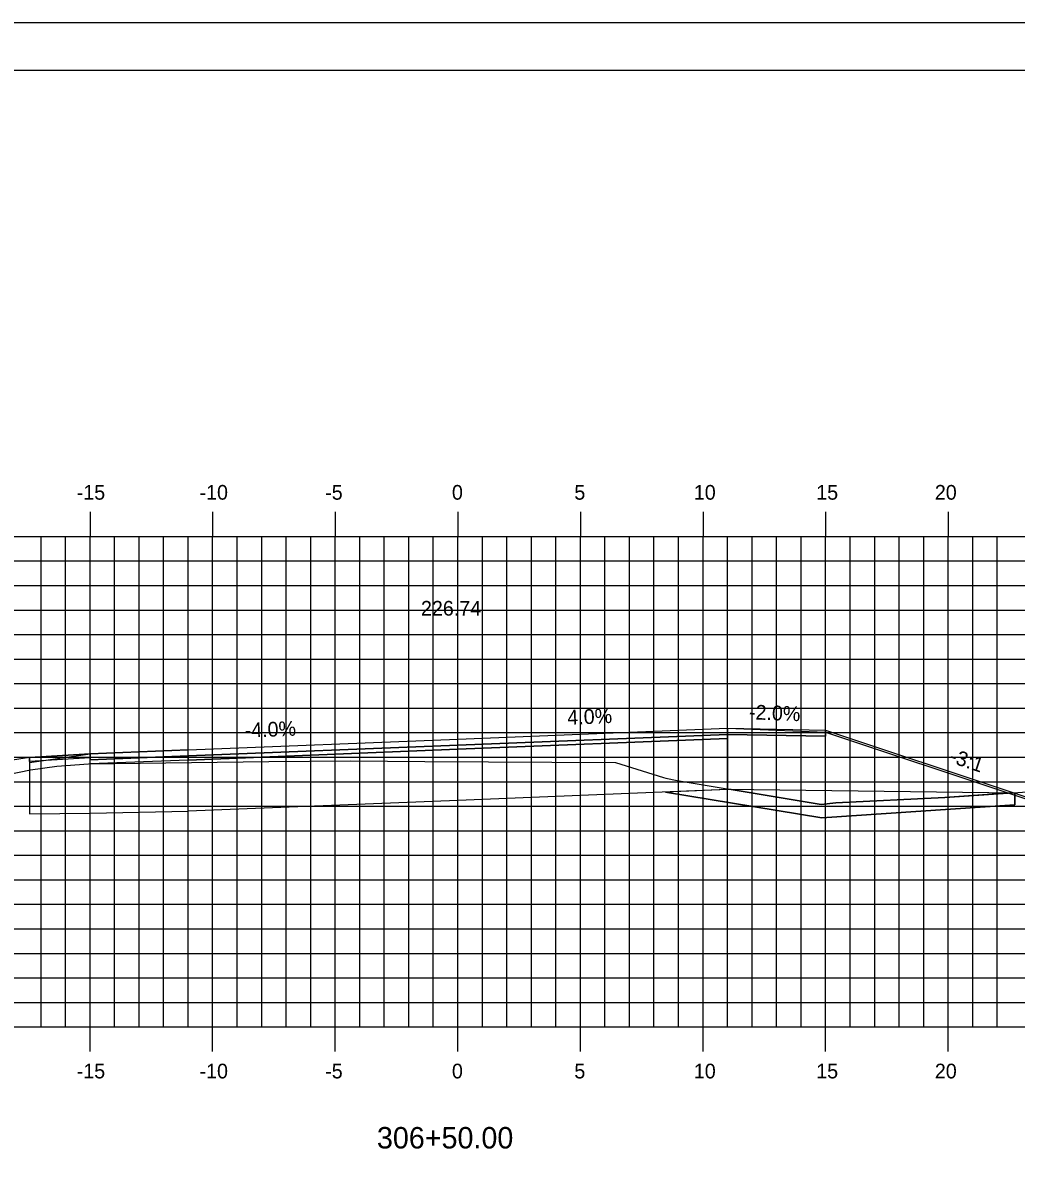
# Model space of a CAD drawing. Extents: x 1137433 to 1137603, y 608981 to 609091.
# Drawn here: x 1137497.92 to 1137538.42, y 609044.46 to 609091.28 of the extents above; entities that cross this region are included whole.
import ezdxf

# ---------------------------------------------------------------- set-up
doc = ezdxf.new("R2010")
doc.units = 0
for name, color, linetype in [('ANNOTATION', 7, 'Continuous'), ('BORDER', 7, 'Continuous'), ('D_Roadway_Centerline', 7, 'Continuous'), ('D_Roadway_Centerline_Text', 7, 'Continuous'), ('D_Roadway_Edge_Shoulder', 7, 'Continuous'), ('D_Roadway_Edge_TW', 7, 'Continuous'), ('D_Roadway_Pavement', 7, 'Continuous'), ('D_Roadway_SlopeLines', 7, 'Continuous'), ('D_Roadway_SubGrade', 7, 'Continuous'), ('H_V ANNOTATION', 7, 'Continuous'), ('MAJOR', 7, 'Continuous'), ('MINOR', 7, 'Continuous'), ('PATTERNING', 7, 'Continuous'), ('PLOT BOUNDARY', 7, 'Continuous'), ('S_Roadway_Centerline', 7, 'Continuous'), ('SHADING', 7, 'Continuous')]:
    doc.layers.add(name, color=color, linetype=linetype)

msp = doc.modelspace()

# ---------------------------------------------------------------- linework, layer by layer
msp.add_lwpolyline([(1137498.181, 609061.117), (1137500.653, 609061.475), (1137504.653, 609061.635), (1137515.653, 609062.075), (1137526.653, 609062.515), (1137530.653, 609062.355), (1137538.376, 609059.781), (1137541.376, 609058.781), (1137541.866, 609059.026), (1137543.116, 609059.579), (1137544.366, 609059.988), (1137545.616, 609060.252), (1137546.866, 609060.373)])
at = {"layer": 'ANNOTATION'}
msp.add_line((1137498.181, 609061.327), (1137477.623, 609058.046), dxfattribs=at)
at = {"layer": 'BORDER'}
msp.add_lwpolyline([(1137440.653, 608984.335), (1137600.653, 608984.335), (1137600.653, 609089.335), (1137440.653, 609089.335)], close=True, dxfattribs=at)
at = {"layer": 'D_Roadway_Edge_Shoulder'}
for points in [[(1137526.653, 609062.515), (1137530.653, 609062.435), (1137530.653, 609062.185), (1137526.653, 609062.265)], [(1137500.653, 609061.475), (1137500.653, 609061.309), (1137498.181, 609061.16), (1137498.181, 609061.327)], [(1137504.653, 609061.635), (1137500.653, 609061.475), (1137500.653, 609061.225), (1137504.653, 609061.385)]]:
    msp.add_lwpolyline(points, close=True, dxfattribs=at)
at = {"layer": 'D_Roadway_Edge_TW'}
for points in [[(1137504.653, 609061.385), (1137504.653, 609061.635), (1137515.653, 609062.075), (1137526.653, 609062.515), (1137526.653, 609062.265), (1137515.653, 609061.825)], [(1137504.653, 609061.219), (1137500.652, 609061.059), (1137500.653, 609061.225), (1137504.653, 609061.385)]]:
    msp.add_lwpolyline(points, close=True, dxfattribs=at)
at = {"layer": 'D_Roadway_Pavement'}
msp.add_lwpolyline([(1137504.653, 609061.219), (1137504.653, 609061.385), (1137515.653, 609061.825), (1137526.653, 609062.265), (1137526.653, 609062.099), (1137515.653, 609061.659)], close=True, dxfattribs=at)
at = {"layer": 'D_Roadway_SlopeLines'}
for points in [[(1137538.376, 609059.861), (1137538.376, 609059.39), (1137530.503, 609058.855), (1137524.125, 609059.914)], [(1137538.376, 609059.861), (1137541.376, 609058.861)]]:
    msp.add_lwpolyline(points, dxfattribs=at)
at = {"layer": 'D_Roadway_SubGrade'}
for points in [[(1137526.653, 609062.099), (1137526.653, 609062.265), (1137530.653, 609062.185), (1137530.653, 609062.435), (1137530.653, 609062.435), (1137538.376, 609059.861), (1137526.653, 609060.015)], [(1137504.653, 609059.135), (1137504.653, 609061.219), (1137515.653, 609061.659), (1137526.653, 609062.099), (1137526.653, 609060.015), (1137515.653, 609059.575)], [(1137498.18, 609059.023), (1137500.653, 609059.055), (1137504.653, 609059.135), (1137504.653, 609061.219), (1137504.653, 609061.385), (1137500.653, 609061.225), (1137500.653, 609061.475), (1137498.181, 609061.327)]]:
    msp.add_lwpolyline(points, close=True, dxfattribs=at)
at = {"layer": 'MAJOR'}
for p, q in [((1137500.653, 609071.337), (1137500.653, 609070.335)), ((1137505.653, 609071.337), (1137505.653, 609070.335)), ((1137510.653, 609071.337), (1137510.653, 609070.335)), ((1137515.653, 609071.337), (1137515.653, 609070.335)), ((1137520.653, 609071.337), (1137520.653, 609070.335)), ((1137525.653, 609071.337), (1137525.653, 609070.335)), ((1137530.653, 609071.337), (1137530.653, 609070.335)), ((1137535.653, 609071.337), (1137535.653, 609070.335)), ((1137445.653, 609070.335), (1137585.653, 609070.335)), ((1137445.653, 609070.335), (1137585.653, 609070.335)), ((1137500.653, 609050.335), (1137500.653, 609070.335)), ((1137505.653, 609050.335), (1137505.653, 609070.335)), ((1137510.653, 609050.335), (1137510.653, 609070.335)), ((1137515.653, 609050.335), (1137515.653, 609070.335)), ((1137520.653, 609050.335), (1137520.653, 609070.335)), ((1137525.653, 609050.335), (1137525.653, 609070.335)), ((1137530.653, 609050.335), (1137530.653, 609070.335)), ((1137535.653, 609050.335), (1137535.653, 609070.335)), ((1137445.653, 609065.335), (1137585.653, 609065.335)), ((1137445.653, 609060.335), (1137585.653, 609060.335)), ((1137445.653, 609055.335), (1137585.653, 609055.335)), ((1137445.653, 609050.335), (1137585.653, 609050.335)), ((1137445.653, 609050.335), (1137585.653, 609050.335)), ((1137500.653, 609049.333), (1137500.653, 609050.335)), ((1137505.653, 609049.333), (1137505.653, 609050.335)), ((1137510.653, 609049.333), (1137510.653, 609050.335)), ((1137515.653, 609049.333), (1137515.653, 609050.335)), ((1137520.653, 609049.333), (1137520.653, 609050.335)), ((1137525.653, 609049.333), (1137525.653, 609050.335)), ((1137530.653, 609049.333), (1137530.653, 609050.335)), ((1137535.653, 609049.333), (1137535.653, 609050.335))]:
    msp.add_line(p, q, dxfattribs=at)
at = {"layer": 'MINOR'}
for p, q in [((1137498.653, 609050.335), (1137498.653, 609070.335)), ((1137499.653, 609050.335), (1137499.653, 609070.335)), ((1137501.653, 609050.335), (1137501.653, 609070.335)), ((1137502.653, 609050.335), (1137502.653, 609070.335)), ((1137503.653, 609050.335), (1137503.653, 609070.335)), ((1137504.653, 609050.335), (1137504.653, 609070.335)), ((1137506.653, 609050.335), (1137506.653, 609070.335)), ((1137507.653, 609050.335), (1137507.653, 609070.335)), ((1137508.653, 609050.335), (1137508.653, 609070.335)), ((1137509.653, 609050.335), (1137509.653, 609070.335)), ((1137511.653, 609050.335), (1137511.653, 609070.335)), ((1137512.653, 609050.335), (1137512.653, 609070.335)), ((1137513.653, 609050.335), (1137513.653, 609070.335)), ((1137514.653, 609050.335), (1137514.653, 609070.335)), ((1137516.653, 609050.335), (1137516.653, 609070.335)), ((1137517.653, 609050.335), (1137517.653, 609070.335)), ((1137518.653, 609050.335), (1137518.653, 609070.335)), ((1137519.653, 609050.335), (1137519.653, 609070.335)), ((1137521.653, 609050.335), (1137521.653, 609070.335)), ((1137522.653, 609050.335), (1137522.653, 609070.335)), ((1137523.653, 609050.335), (1137523.653, 609070.335)), ((1137524.653, 609050.335), (1137524.653, 609070.335)), ((1137526.653, 609050.335), (1137526.653, 609070.335)), ((1137527.653, 609050.335), (1137527.653, 609070.335)), ((1137528.653, 609050.335), (1137528.653, 609070.335)), ((1137529.653, 609050.335), (1137529.653, 609070.335)), ((1137531.653, 609050.335), (1137531.653, 609070.335)), ((1137532.653, 609050.335), (1137532.653, 609070.335)), ((1137533.653, 609050.335), (1137533.653, 609070.335)), ((1137534.653, 609050.335), (1137534.653, 609070.335)), ((1137536.653, 609050.335), (1137536.653, 609070.335)), ((1137537.653, 609050.335), (1137537.653, 609070.335)), ((1137445.653, 609069.335), (1137585.653, 609069.335)), ((1137445.653, 609068.335), (1137585.653, 609068.335)), ((1137445.653, 609067.335), (1137585.653, 609067.335)), ((1137445.653, 609066.335), (1137585.653, 609066.335)), ((1137445.653, 609064.335), (1137585.653, 609064.335)), ((1137445.653, 609063.335), (1137585.653, 609063.335)), ((1137445.653, 609062.335), (1137585.653, 609062.335)), ((1137445.653, 609061.335), (1137585.653, 609061.335)), ((1137445.653, 609059.335), (1137585.653, 609059.335)), ((1137445.653, 609058.335), (1137585.653, 609058.335)), ((1137445.653, 609057.335), (1137585.653, 609057.335)), ((1137445.653, 609056.335), (1137585.653, 609056.335)), ((1137445.653, 609054.335), (1137585.653, 609054.335)), ((1137445.653, 609053.335), (1137585.653, 609053.335)), ((1137445.653, 609052.335), (1137585.653, 609052.335)), ((1137445.653, 609051.335), (1137585.653, 609051.335))]:
    msp.add_line(p, q, dxfattribs=at)
at = {"layer": 'PATTERNING'}
msp.add_line((1137526.653, 609062.515), (1137530.653, 609062.435), dxfattribs=at)
at = {"layer": 'PLOT BOUNDARY'}
msp.add_lwpolyline([(1137432.56, 608981.276), (1137602.56, 608981.276), (1137602.56, 609091.276), (1137432.56, 609091.276)], close=True, dxfattribs=at)
at = {"layer": 'S_Roadway_Centerline'}
msp.add_lwpolyline([(1137445.653, 609057.929), (1137453.384, 609057.836), (1137462.728, 609057.933), (1137472.775, 609058.023), (1137479.462, 609058.055), (1137482.576, 609058.161), (1137486.003, 609058.295), (1137491.397, 609059.425), (1137498.22, 609060.819), (1137499.297, 609060.966), (1137500.585, 609061.068), (1137507.942, 609061.156), (1137511.268, 609061.183), (1137514.305, 609061.154), (1137522.089, 609061.113), (1137524.047, 609060.511), (1137524.139, 609060.485), (1137524.594, 609060.38), (1137530.466, 609059.405), (1137531.069, 609059.477), (1137535.521, 609059.696), (1137539.278, 609059.952)], dxfattribs=at)
at = {"layer": 'SHADING'}
for p, q in [((1137526.653, 609060.015), (1137524.125, 609059.914)), ((1137526.801, 609060.013), (1137526.653, 609060.015)), ((1137538.376, 609059.861), (1137538.014, 609059.866))]:
    msp.add_line(p, q, dxfattribs=at)
for points in [[(1137524.125, 609059.914), (1137530.503, 609058.855), (1137538.376, 609059.39), (1137538.376, 609059.861)], [(1137538.014, 609059.866), (1137535.521, 609059.696), (1137531.069, 609059.477), (1137530.466, 609059.405), (1137526.801, 609060.013)]]:
    msp.add_lwpolyline(points, dxfattribs=at)

# ---------------------------------------------------------------- texts
at = {"layer": 'ANNOTATION'}
for s, rotation, p in [('4.0%', 2.2906, (1137520.129, 609062.655)), ('-2.0%', 357.7094, (1137527.517, 609062.882)), ('-4.0%', 2.2906, (1137506.969, 609062.129)), ('-3:1', 341.5652, (1137535.664, 609061.139))]:
    msp.add_text(s, height=0.6, rotation=rotation, dxfattribs=at).set_placement(p)
at = {"layer": 'D_Roadway_Centerline'}
for s, p in [('C', (1137515.648, 609062.075)), ('L', (1137515.653, 609062.068))]:
    msp.add_text(s, height=0.0146, dxfattribs=at).set_placement(p)
at = {"layer": 'D_Roadway_Centerline_Text'}
msp.add_text('226.74', height=0.6, dxfattribs=at).set_placement((1137514.149, 609067.107))
at = {"layer": 'H_V ANNOTATION'}
for s, height, p in [('-15', 0.6, (1137500.11, 609071.835)), ('-10', 0.6, (1137505.118, 609071.835)), ('-5', 0.6, (1137510.243, 609071.835)), ('0', 0.6, (1137515.412, 609071.835)), ('5', 0.6, (1137520.404, 609071.835)), ('10', 0.6, (1137525.278, 609071.835)), ('15', 0.6, (1137530.27, 609071.835)), ('20', 0.6, (1137535.107, 609071.835)), ('-15', 0.6, (1137500.11, 609048.235)), ('-10', 0.6, (1137505.118, 609048.235)), ('-5', 0.6, (1137510.243, 609048.235)), ('0', 0.6, (1137515.412, 609048.235)), ('5', 0.6, (1137520.404, 609048.235)), ('10', 0.6, (1137525.278, 609048.235)), ('15', 0.6, (1137530.27, 609048.235)), ('20', 0.6, (1137535.107, 609048.235)), ('306+50.00', 0.875, (1137512.352, 609045.378))]:
    msp.add_text(s, height=height, dxfattribs=at).set_placement(p)
at = {"layer": 'S_Roadway_Centerline'}
for s, p in [('L', (1137511.259, 609061.175)), ('C', (1137511.262, 609061.183))]:
    msp.add_text(s, height=0.0146, dxfattribs=at).set_placement(p)

doc.saveas('drawing.dxf')
